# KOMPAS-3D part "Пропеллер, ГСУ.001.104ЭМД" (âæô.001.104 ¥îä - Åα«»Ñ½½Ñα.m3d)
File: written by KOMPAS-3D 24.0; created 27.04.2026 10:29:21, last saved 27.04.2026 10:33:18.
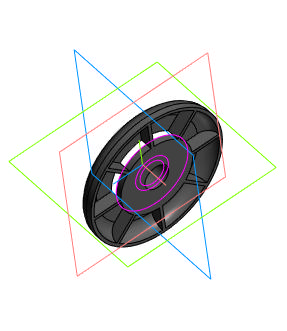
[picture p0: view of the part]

Document properties: Автор: USG_411; Полное имя файла: C:\Users\USG_411\Desktop\ГМ2704_411-15\ГСУ.001.104 ЭМД - Пропеллер.m3d

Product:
- Part/product: Пропеллер  | designation ГСУ.001.104ЭМД
    Масса: 0.029778

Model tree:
1. Эскиз:1
2. Элемент выдавливания:1
     Расстояние 1 = 6
3. Эскиз:2  (with: Грань.Элемент выдавливания:1)
4. Элемент выдавливания:2
     Расстояние 2 = 4
5. Скругление:1  (with: Ребро.Элемент выдавливания:1)
     Радиус = 4
6. Скругление:2  (with: Ребро.Элемент выдавливания:2)
     Радиус = 4
7. Эскиз:3  (with: Грань.Элемент выдавливания:2)
8. Элемент выдавливания:3
     Расстояние 1 = 4
9. Эскиз:4  (with: Грань.Элемент выдавливания:3)
10. Элемент выдавливания:4
11. Эскиз:5  (with: Грань.Элемент выдавливания:3, Грань.Скругление:2, Ребро.Элемент выдавливания:3)
12. Элемент выдавливания:5
     Расстояние 1 = 1
13. Массив по концентрической сетке:1  (with: Элемент выдавливания:5, Эскиз:5, Грань.Элемент выдавливания:4)  (8 pattern instances)
     Шаг 2 = 360
14. Эскиз:6  (with: Ребро.Скругление:1, Грань.Элемент выдавливания:4, Вершина.Элемент выдавливания:5)
15. Элемент вращения:1
     Угол 1 = 360
16. Эскиз:7  (with: Грань.Элемент вращения:1)
17. Элемент выдавливания:6
     Расстояние 2 = 2
18. Эскиз:8  (with: Грань.Элемент выдавливания:6, Ребро.Элемент выдавливания:6)
19. Элемент выдавливания:7
     Расстояние 1 = 4

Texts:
  Точка начала. Х
  Точка начала. Y
  Точка начала. Z
  ГСУ.001.104
  ГСУ.001.104 ЭМД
